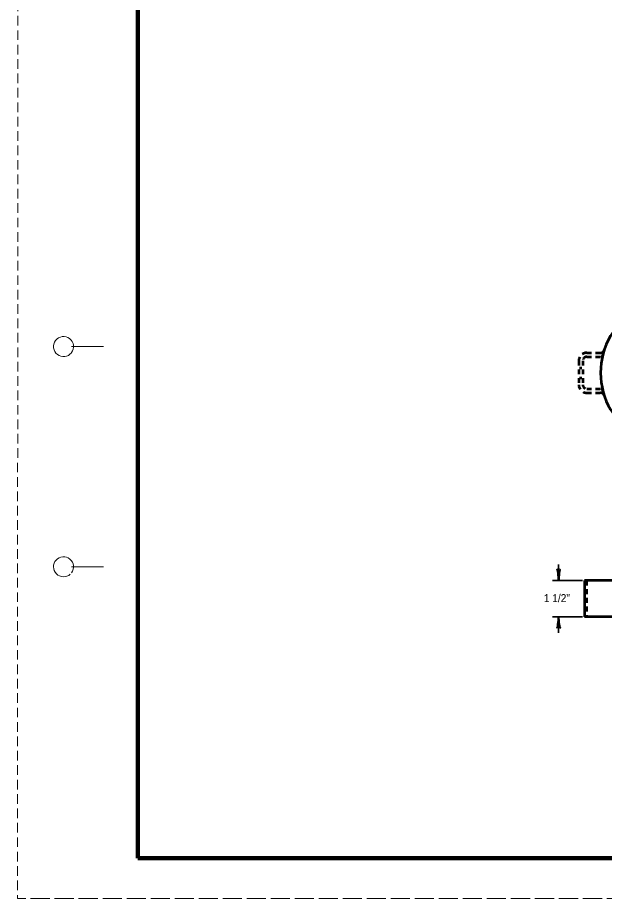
# Model space of a CAD drawing. Extents: x -368 to 312, y -34 to 406.
# Drawn here: x -368 to -221.3, y -34 to 186 of the extents above; entities that cross this region are included whole.
import ezdxf
from ezdxf.enums import TextEntityAlignment as Align

# ---------------------------------------------------------------- set-up
doc = ezdxf.new("R2010")
doc.units = 0
doc.header["$LTSCALE"] = 0.8
for name, pattern in [('LONG_DASHED', [7.5, 6, -1.5]), ('MEDIUM_DASHED', [4.5, 3, -1.5]), ('SHORT_DASHED', [2.7, 1.5, -1.2])]:
    doc.linetypes.add(name, pattern=pattern)
doc.layers.add('1', color=7, linetype='Continuous', lineweight=53)
doc.layers.add('61', color=7, linetype='Continuous', lineweight=35)

msp = doc.modelspace()

# ---------------------------------------------------------------- linework, layer by layer
at = {"layer": '1', "linetype": 'MEDIUM_DASHED', "lineweight": 13}
msp.add_line((-367.9015, 406.0392), (-367.9615, -34.0007), dxfattribs=at)
at = {"layer": '1', "linetype": 'SHORT_DASHED'}
for p, q in [((-225.7114, 102.2942), (-222.3022, 102.2942)), ((-225.7114, 101.2942), (-222.2114, 101.2942)), ((-227.7114, 100.2942), (-227.7114, 94.2942)), ((-226.7114, 100.2942), (-226.7114, 94.2942)), ((-225.7114, 93.2942), (-222.2114, 93.2942)), ((-225.7114, 92.2942), (-222.3022, 92.2942)), ((-225.7802, 45.3725), (-225.7802, 36.3725))]:
    msp.add_line(p, q, dxfattribs=at)
at = {"layer": '1'}
for p, q in [((-227.5114, 98.5442), (-226.9114, 98.5442)), ((-227.5114, 96.0442), (-226.9114, 96.0442)), ((-215.0302, 45.3725), (-226.2802, 45.3725)), ((-226.2802, 45.3725), (-226.2802, 36.3725)), ((-215.0302, 36.3725), (-226.2802, 36.3725))]:
    msp.add_line(p, q, dxfattribs=at)
at = {"layer": '1', "lineweight": 35}
for p, q in [((-232.7518, 45.3725), (-232.7518, 49.4253)), ((-226.7802, 45.3725), (-234.2802, 45.3725)), ((-226.7802, 36.3725), (-234.2802, 36.3725)), ((-232.7518, 32.3725), (-232.7518, 36.3725))]:
    msp.add_line(p, q, dxfattribs=at)
at = {"layer": '1'}
msp.add_arc((-204.0904, 97.2942), 18.1748, 119.23653, 240.76348, dxfattribs=at)
at = {"layer": '1', "linetype": 'SHORT_DASHED'}
for centre, radius, start, end in [((-225.7114, 100.2942), 2, 90, 180), ((-225.7114, 100.2942), 1, 90, 180), ((-222.3022, 103.2942), 1, 270, 341.76525), ((-222.2114, 101.7942), 0.5, 270, 0), ((-225.7114, 94.2942), 2, 180, 270), ((-225.7114, 94.2942), 1, 180, 270), ((-222.2114, 92.7942), 0.5, 0, 90), ((-222.3022, 91.2812), 1, 18.23475, 90)]:
    msp.add_arc(centre, radius, start, end, dxfattribs=at)
at = {"layer": '1', "lineweight": 40}
for centre, major_axis, ratio, start_param, end_param in [((-233.0281, 46.4637), (0.1562, -1.7857), 0.122415, 0.89635335, 3.14159265), ((-233.0281, 46.4637), (0.1562, -1.7857), 0.122415, 0.89635335, 3.14159265), ((-232.5402, 46.493), (-0.1757, -1.7565), 0.07063, 3.14071475, 5.41810995), ((-232.5402, 46.493), (-0.1757, -1.7565), 0.07063, 3.14071475, 5.41810995), ((-232.9634, 35.252), (0.1757, 1.7565), 0.07063, 3.14071475, 5.41810995), ((-232.9634, 35.252), (0.1757, 1.7565), 0.07063, 3.14071475, 5.41810995), ((-232.4755, 35.2813), (-0.1562, 1.7857), 0.122415, 0.89635335, 3.14159265), ((-232.4755, 35.2813), (-0.1562, 1.7857), 0.122415, 0.89635335, 3.14159265)]:
    msp.add_ellipse(centre, major_axis=major_axis, ratio=ratio, start_param=start_param, end_param=end_param, dxfattribs=at)
at = {"layer": '61', "lineweight": 13}
for p, q in [((-354.4815, 103.8593), (-346.4815, 103.8593)), ((-354.4615, 48.8392), (-346.4815, 48.8392))]:
    msp.add_line(p, q, dxfattribs=at)
at = {"layer": '61', "lineweight": 158}
msp.add_line((301.1585, -24.0008), (-337.9015, -23.9808), dxfattribs=at)
at = {"layer": '61', "linetype": 'LONG_DASHED', "lineweight": 13}
msp.add_line((312.0985, -33.9808), (-367.9615, -34.0007), dxfattribs=at)
at = {"layer": '61', "lineweight": 158}
msp.add_lwpolyline([(301.1385, 396.0392), (-337.9015, 396.0392), (-337.9015, -23.9808)], dxfattribs=at)
at = {"layer": '61', "lineweight": 13}
for centre, start, end in [((-356.4837, 103.8405), 322.67175, 321.71615), ((-356.4837, 48.8405), 323.13009, 312.31439)]:
    msp.add_arc(centre, 2.5, start, end, dxfattribs=at)

# ---------------------------------------------------------------- texts
at = {"layer": '1', "width": 0.95}
msp.add_text('1 1/2"', height=2, dxfattribs=at).set_placement((-233.1864, 39.9999), align=Align.CENTER)

doc.saveas('drawing.dxf')
